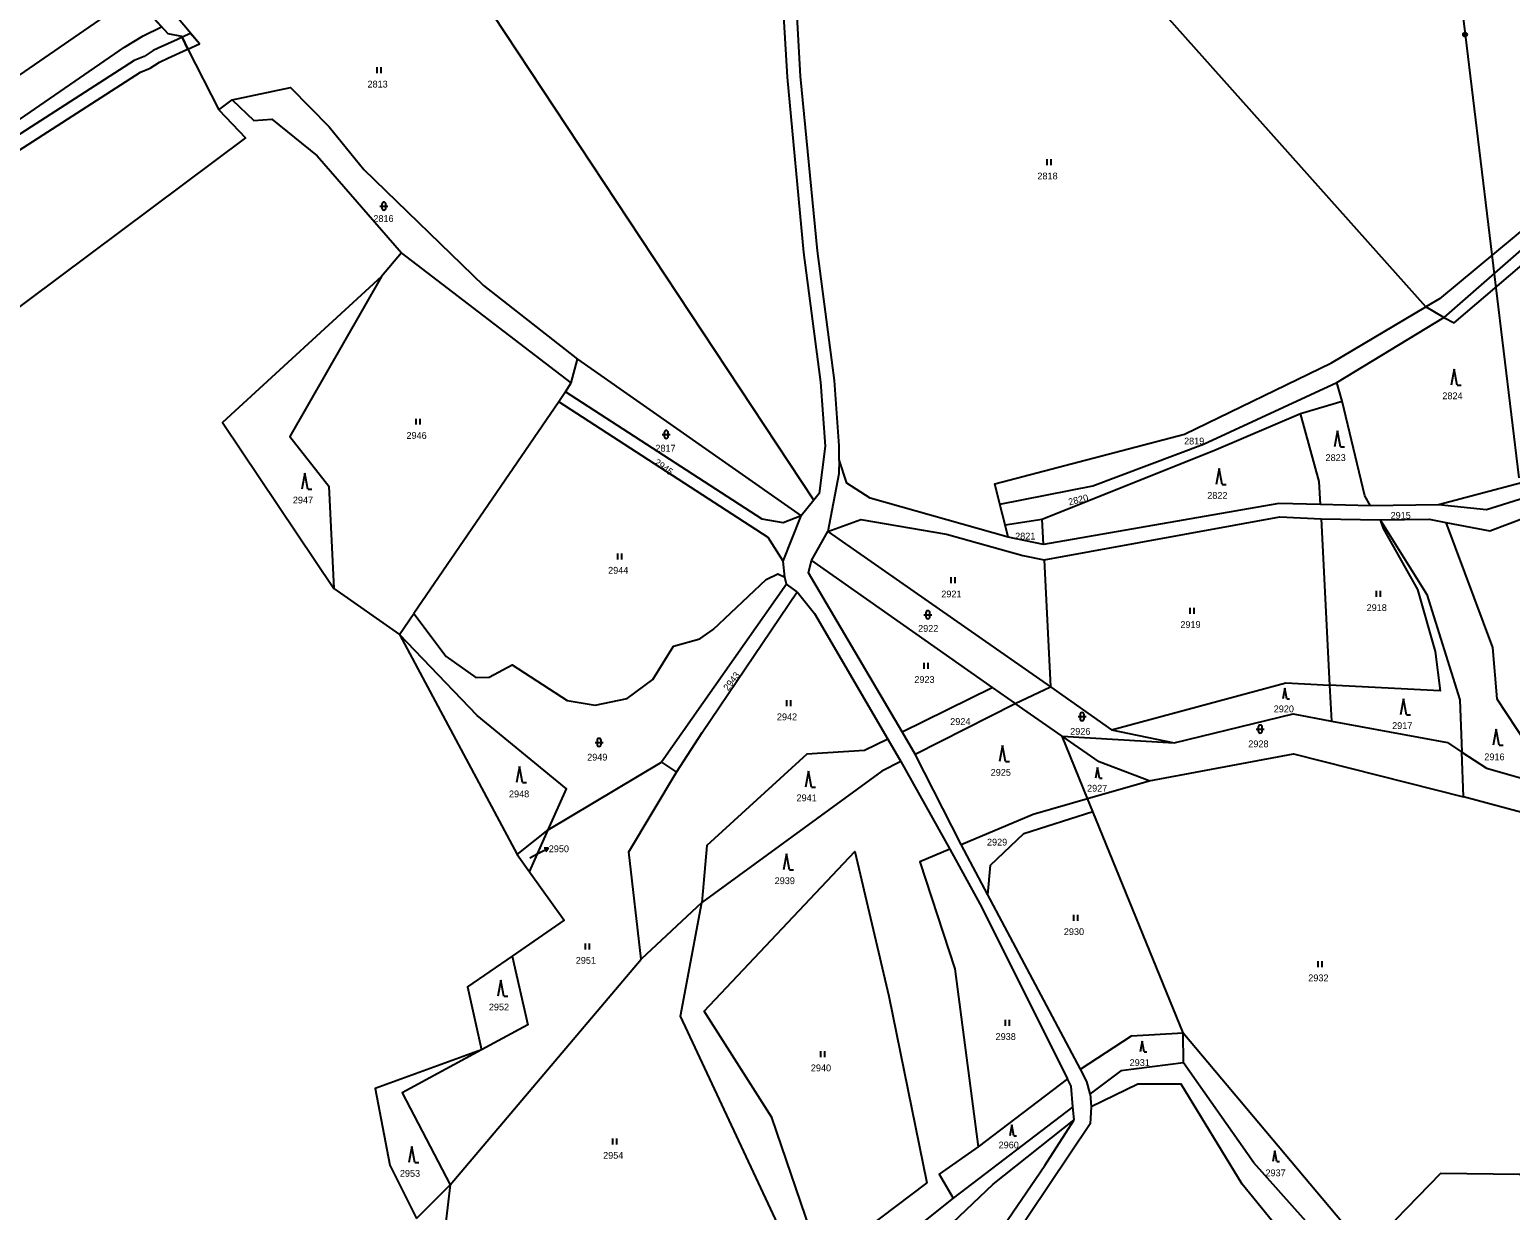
# Model space of a CAD drawing. Extents: x -504988 to -494607, y -1123820 to -1114018.
# Drawn here: x -497021.1 to -496650.7, y -1121578.3 to -1121283 of the extents above; entities that cross this region are included whole.
import ezdxf

# ---------------------------------------------------------------- set-up
doc = ezdxf.new("R2010")
doc.units = 0
for name, color, linetype in [('Hranice parcel', 7, 'Continuous'), ('Parcelní čísla', 7, 'Continuous'), ('Pop  PČ popisy', 7, 'Continuous'), ('Poz předměty', 7, 'Continuous'), ('Věcná břemena k části', 7, 'Continuous'), ('Značky kultur', 7, 'Continuous')]:
    doc.layers.add(name, color=color, linetype=linetype)

msp = doc.modelspace()

# ---------------------------------------------------------------- linework, layer by layer
at = {"layer": 'Hranice parcel'}
for p, q in [((-496824.94, -1121400.71), (-496928.4, -1121244.15)), ((-496981.48, -1121287.89), (-496973.8, -1121303.07)), ((-496973.8, -1121303.07), (-496970.4, -1121300.6)), ((-496928.1, -1121338.83), (-496933.09, -1121344.78)), ((-496885.6, -1121371.41), (-496928.1, -1121338.83)), ((-496667.38, -1121355.04), (-496671.83, -1121352.39)), ((-496694.09, -1121371.3), (-496667.38, -1121355.04)), ((-496885.6, -1121371.41), (-496884.09, -1121365.43)), ((-496884.09, -1121365.43), (-496828.07, -1121404.66)), ((-496887.05, -1121373.63), (-496885.6, -1121371.41)), ((-496692.78, -1121375.94), (-496694.09, -1121371.3)), ((-496887.05, -1121373.63), (-496888.69, -1121376.14)), ((-496888.69, -1121376.14), (-496924.95, -1121429.06)), ((-496703.19, -1121379.08), (-496692.78, -1121375.94)), ((-496824.94, -1121400.71), (-496828.07, -1121404.66)), ((-496832.57, -1121416.01), (-496828.07, -1121404.66)), ((-496777.11, -1121406.92), (-496778.37, -1121401.76)), ((-496685.69, -1121402.16), (-496698.17, -1121401.84)), ((-496668.66, -1121401.9), (-496685.69, -1121402.16)), ((-496825.49, -1121415.83), (-496821.43, -1121408.53)), ((-496821.43, -1121408.53), (-496765.73, -1121447.42)), ((-496777.11, -1121406.92), (-496767.82, -1121405.47)), ((-496776.29, -1121410), (-496777.11, -1121406.92)), ((-496767.51, -1121411.82), (-496767.82, -1121405.47)), ((-496698, -1121405.35), (-496683.24, -1121405.64)), ((-496698, -1121405.35), (-496695.91, -1121446.98)), ((-496767.51, -1121411.82), (-496776.29, -1121410)), ((-496832.23, -1121419.94), (-496832.57, -1121416.01)), ((-496825.49, -1121415.83), (-496780.3, -1121447.56)), ((-496767.3, -1121415.62), (-496765.73, -1121447.42)), ((-496831.81, -1121421.77), (-496832.23, -1121419.94)), ((-496945.04, -1121422.83), (-496928.54, -1121434.3)), ((-496831.81, -1121421.77), (-496863.07, -1121466.22)), ((-496829.09, -1121423.64), (-496831.81, -1121421.77)), ((-496928.54, -1121434.3), (-496924.95, -1121429.06)), ((-496928.54, -1121434.3), (-496899.13, -1121489.34)), ((-496802.88, -1121458.7), (-496780.3, -1121447.56)), ((-496780.3, -1121447.56), (-496774.61, -1121451.55)), ((-496774.61, -1121451.55), (-496765.73, -1121447.42)), ((-496765.73, -1121447.42), (-496750.47, -1121458.17)), ((-496695.91, -1121446.98), (-496695.46, -1121455.98)), ((-496799.61, -1121464.28), (-496774.61, -1121451.55)), ((-496762.86, -1121459.74), (-496774.61, -1121451.55)), ((-496806.44, -1121460.46), (-496803.16, -1121466.09)), ((-496799.61, -1121464.28), (-496802.88, -1121458.7)), ((-496762.86, -1121459.74), (-496734.81, -1121461.39)), ((-496756.48, -1121475.34), (-496762.86, -1121459.74)), ((-496750.47, -1121458.17), (-496734.81, -1121461.39)), ((-496788.09, -1121486.83), (-496799.61, -1121464.28)), ((-496662.4, -1121474.88), (-496662.87, -1121463.73)), ((-496891.35, -1121483.17), (-496863.07, -1121466.22)), ((-496863.07, -1121466.22), (-496859.31, -1121468.79)), ((-496803.16, -1121466.09), (-496790.92, -1121488.01)), ((-496756.48, -1121475.34), (-496741.08, -1121470.91)), ((-496755.17, -1121478.55), (-496756.48, -1121475.34)), ((-496620.4, -1121486.22), (-496662.4, -1121474.88)), ((-496732.53, -1121533.92), (-496755.17, -1121478.55)), ((-496899.13, -1121489.34), (-496891.35, -1121483.17)), ((-496896.02, -1121493.69), (-496891.35, -1121483.17)), ((-496899.13, -1121489.34), (-496896.02, -1121493.69)), ((-496781.41, -1121499.41), (-496788.09, -1121486.83)), ((-496852.92, -1121501.35), (-496868.16, -1121515.55)), ((-496758.24, -1121543.03), (-496781.41, -1121499.41)), ((-496915.94, -1121571.97), (-496868.16, -1121515.55)), ((-496732.5, -1121541.44), (-496732.53, -1121533.92)), ((-496732.53, -1121533.92), (-496679.69, -1121596.75)), ((-496761.51, -1121545.43), (-496783.8, -1121562.43)), ((-496755.85, -1121549.23), (-496755.6, -1121552.41)), ((-496760.11, -1121552.45), (-496790.08, -1121575.29)), ((-496759.8, -1121555.72), (-496760.11, -1121552.45)), ((-496924.29, -1121580.35), (-496915.94, -1121571.97)), ((-496915.94, -1121571.97), (-496920.35, -1121610.08)), ((-496790.08, -1121575.29), (-496817.45, -1121597.02))]:
    msp.add_line(p, q, dxfattribs=at)
for points in [[(-496848.25, -1121142.03), (-496843.63, -1121149.55), (-496842.8, -1121152.45), (-496838.16, -1121184.95), (-496831.64, -1121294.95), (-496827.52, -1121338.76), (-496823.26, -1121371.18), (-496822.08, -1121387.23), (-496823.6, -1121399.02), (-496824.94, -1121400.71)], [(-496671.83, -1121352.39), (-496785.15, -1121225.31), (-496830.93, -1121246.77)], [(-497027.04, -1121239.69), (-496986.49, -1121284.04), (-496983.12, -1121284.65), (-496981.48, -1121287.89)], [(-496981.48, -1121287.89), (-496978.57, -1121286.57), (-497015.21, -1121242.93)], [(-496818.64, -1121390.63), (-496818.58, -1121387.13), (-496819.78, -1121370.83), (-496824.04, -1121338.37), (-496828.25, -1121294.69), (-496830.93, -1121246.77)], [(-496970.4, -1121300.6), (-496955.8, -1121297.55), (-496946.16, -1121307.32), (-496937.53, -1121318.02), (-496907.55, -1121347.01), (-496884.09, -1121365.43)], [(-496970.4, -1121300.6), (-496965, -1121305.73), (-496960.54, -1121305.42), (-496949.18, -1121314.58), (-496928.1, -1121338.83)], [(-496973.8, -1121303.07), (-496967.1, -1121310.13), (-497060.54, -1121379.84), (-497153.97, -1121449.54), (-497260.82, -1121531.25), (-497367.67, -1121612.95), (-497514.07, -1121725.27), (-497650.99, -1121827.6), (-497729.46, -1121888.34), (-497836.33, -1121970.93), (-497882.09, -1122005.22)], [(-496622.71, -1121308.03), (-496636.01, -1121323.43), (-496668.45, -1121350.39), (-496671.83, -1121352.39)], [(-496622.71, -1121308.03), (-496628.61, -1121321.12), (-496667.38, -1121355.04)], [(-496667.38, -1121355.04), (-496664.77, -1121356.36), (-496626.79, -1121324.03), (-496643.72, -1121366.96), (-496641.34, -1121368.36), (-496625.44, -1121332.21)], [(-496933.09, -1121344.78), (-496972.87, -1121381.29), (-496945.04, -1121422.83)], [(-496933.09, -1121344.78), (-496956.02, -1121384.82), (-496946.29, -1121397.26), (-496945.04, -1121422.83)], [(-496778.37, -1121401.76), (-496779.64, -1121396.6), (-496732.23, -1121384.19), (-496695.49, -1121366.35), (-496671.83, -1121352.39)], [(-496620.34, -1121360.24), (-496634.95, -1121356.72), (-496633.53, -1121372.93), (-496638.31, -1121372.79), (-496639.77, -1121389.71), (-496646.34, -1121396), (-496668.66, -1121401.9)], [(-496778.37, -1121401.76), (-496755.18, -1121397.16), (-496727.48, -1121386.73), (-496694.09, -1121371.3)], [(-496828.07, -1121404.66), (-496832.6, -1121406.4), (-496837.86, -1121405.5), (-496887.05, -1121373.63)], [(-496832.57, -1121416.01), (-496836.36, -1121410.03), (-496888.69, -1121376.14)], [(-496767.82, -1121405.47), (-496724.29, -1121388.08), (-496703.19, -1121379.08)], [(-496698.17, -1121401.84), (-496698.51, -1121396.09), (-496703.19, -1121379.08)], [(-496685.69, -1121402.16), (-496687.11, -1121399.61), (-496692.78, -1121375.94)], [(-496818.64, -1121390.63), (-496818.69, -1121394.14), (-496821.43, -1121408.53)], [(-496776.29, -1121410), (-496810.86, -1121400.24), (-496816.65, -1121396.46), (-496818.64, -1121390.63)], [(-496558.08, -1121460.12), (-496564.28, -1121460.43), (-496569.68, -1121458.96), (-496588.54, -1121447.1), (-496598.53, -1121439.12), (-496623.23, -1121401.96), (-496630.14, -1121397.89), (-496637.5, -1121397.15), (-496656.69, -1121403.1), (-496668.66, -1121401.9)], [(-496698.17, -1121401.84), (-496708.6, -1121401.57), (-496767.51, -1121411.82)], [(-496767.3, -1121415.62), (-496708.4, -1121404.87), (-496698, -1121405.35)], [(-496666.89, -1121406.29), (-496655.87, -1121408.36), (-496642.6, -1121403.41), (-496634.03, -1121402.52), (-496627.92, -1121405.3), (-496623.56, -1121408.29), (-496600.71, -1121442.49), (-496590.86, -1121450.37)], [(-496821.43, -1121408.53), (-496813.17, -1121405.57), (-496791.74, -1121409.22), (-496772.62, -1121414.57), (-496767.3, -1121415.62)], [(-496683.24, -1121405.64), (-496682.54, -1121407.78), (-496673.95, -1121423.07), (-496669.56, -1121438.61), (-496668.23, -1121448.39), (-496695.91, -1121446.98)], [(-496683.24, -1121405.64), (-496671.01, -1121405.51), (-496666.89, -1121406.29)], [(-496683.24, -1121405.64), (-496671.63, -1121424.3), (-496663.33, -1121450.7), (-496662.87, -1121463.73)], [(-496666.89, -1121406.29), (-496655.19, -1121437.57), (-496654.1, -1121450.38), (-496646.83, -1121461.45), (-496616.96, -1121474.47)], [(-496802.88, -1121458.7), (-496826.24, -1121418.88), (-496825.49, -1121415.83)], [(-496924.95, -1121429.06), (-496916.88, -1121439.84), (-496909.45, -1121445.04), (-496906.15, -1121445), (-496900.38, -1121441.89), (-496886.67, -1121450.86), (-496879.64, -1121452.02), (-496871.65, -1121450.35), (-496865.24, -1121445.55), (-496860.04, -1121437.24), (-496853.43, -1121435.4), (-496850.09, -1121433.09), (-496836.83, -1121420.56), (-496833.93, -1121419.13), (-496832.23, -1121419.94)], [(-496859.31, -1121468.79), (-496852.85, -1121458.85), (-496829.09, -1121423.64)], [(-496829.09, -1121423.64), (-496824.76, -1121429.05), (-496806.44, -1121460.46)], [(-496891.35, -1121483.17), (-496886.78, -1121472.9), (-496909.18, -1121454.59), (-496928.54, -1121434.3)], [(-496750.47, -1121458.17), (-496706.91, -1121446.42), (-496695.91, -1121446.98)], [(-496734.81, -1121461.39), (-496705.03, -1121454.2), (-496695.46, -1121455.98)], [(-496695.46, -1121455.98), (-496666.47, -1121461.37), (-496662.87, -1121463.73)], [(-496806.44, -1121460.46), (-496812.23, -1121463.32), (-496826.72, -1121464.23), (-496851.72, -1121487.12), (-496852.92, -1121501.35)], [(-496741.08, -1121470.91), (-496753.54, -1121466.19), (-496762.86, -1121459.74)], [(-496741.08, -1121470.91), (-496704.99, -1121464.18), (-496662.4, -1121474.88)], [(-496662.87, -1121463.73), (-496656.68, -1121467.79), (-496606.05, -1121482.18)], [(-496803.16, -1121466.09), (-496807.96, -1121468.54), (-496852.92, -1121501.35)], [(-496868.16, -1121515.55), (-496871.17, -1121488.67), (-496859.31, -1121468.79)], [(-496788.09, -1121486.83), (-496770.11, -1121479.26), (-496756.48, -1121475.34)], [(-496781.41, -1121499.41), (-496780.71, -1121491.98), (-496772.38, -1121484.05), (-496755.17, -1121478.55)], [(-496796.66, -1121571.42), (-496819.87, -1121588.98), (-496825.78, -1121583.49), (-496835.43, -1121555.08), (-496852.36, -1121528.53), (-496814.67, -1121488.62), (-496806.18, -1121524.73), (-496796.66, -1121571.42)], [(-496790.92, -1121488.01), (-496798.45, -1121491.19), (-496789.69, -1121517.91), (-496783.8, -1121562.43)], [(-496790.92, -1121488.01), (-496783.41, -1121501.67), (-496761.51, -1121545.43)], [(-496896.02, -1121493.69), (-496887.42, -1121505.73), (-496900.39, -1121514.74)], [(-496832.12, -1121585.69), (-496858.26, -1121529.75), (-496852.92, -1121501.35)], [(-496900.39, -1121514.74), (-496911.53, -1121522.47), (-496908.04, -1121538.23)], [(-496900.39, -1121514.74), (-496896.44, -1121531.96), (-496908.04, -1121538.23)], [(-496758.24, -1121543.03), (-496745.45, -1121534.72), (-496732.53, -1121533.92)], [(-496908.04, -1121538.23), (-496934.65, -1121547.87), (-496930.98, -1121567.06), (-496924.29, -1121580.35)], [(-496908.04, -1121538.23), (-496927.88, -1121548.95), (-496915.94, -1121571.97)], [(-496732.5, -1121541.44), (-496748.16, -1121543.43), (-496755.85, -1121549.23)], [(-496686.13, -1121598.72), (-496714.85, -1121566.43), (-496732.5, -1121541.44)], [(-496760.11, -1121552.45), (-496760.6, -1121547.25), (-496761.51, -1121545.43)], [(-496755.85, -1121549.23), (-496756.69, -1121546.13), (-496758.24, -1121543.03)], [(-496758.17, -1121707.39), (-496746.55, -1121684.08), (-496750.96, -1121648.86), (-496743.63, -1121632.12), (-496731.41, -1121616.02), (-496714.73, -1121605.77), (-496695.15, -1121599.6), (-496717.82, -1121571.78), (-496733.06, -1121546.75), (-496743.91, -1121546.74), (-496755.6, -1121552.41)], [(-496755.6, -1121552.41), (-496755.84, -1121556.71), (-496786.34, -1121602.24), (-496790.93, -1121617.84), (-496789.5, -1121631.19), (-496787.93, -1121654.85), (-496788.06, -1121674.86), (-496781.27, -1121683.85), (-496768.89, -1121690.38), (-496761.24, -1121698.29), (-496758.17, -1121707.39)], [(-496810.31, -1121600.51), (-496780.06, -1121571.77), (-496759.8, -1121555.72)], [(-496794.98, -1121617.43), (-496790.01, -1121600.53), (-496767.13, -1121567.08), (-496759.8, -1121555.72)], [(-496783.8, -1121562.43), (-496793.6, -1121569.28), (-496790.08, -1121575.29)], [(-496628.32, -1121586.51), (-496631.2, -1121576.69), (-496648.43, -1121569.4), (-496668.19, -1121569.15), (-496679.47, -1121580.69), (-496681.86, -1121588.4), (-496679.69, -1121596.75)]]:
    msp.add_lwpolyline(points, dxfattribs=at)
at = {"layer": 'Pop  PČ popisy'}
for p, q in [((-496895.98, -1121490.14), (-496893.95, -1121489.13)), ((-496893.95, -1121489.13), (-496891.28, -1121487.77)), ((-496891.28, -1121487.77), (-496892.4, -1121487.78)), ((-496891.28, -1121487.77), (-496891.94, -1121488.67))]:
    msp.add_line(p, q, dxfattribs=at)
at = {"layer": 'Poz předměty'}
for p, q in [((-496673.23, -1121192.05), (-496662.04, -1121284.27)), ((-496662.04, -1121284.27), (-496648.56, -1121395.11))]:
    msp.add_line(p, q, dxfattribs=at)
for radius in [0.5, 0.4, 0.3, 0.2, 0.1]:
    msp.add_circle((-496662.04, -1121284.27), radius, dxfattribs=at)
at = {"layer": 'Věcná břemena k části'}
for points in [[(-497811.58, -1121879.55), (-497093.4, -1121353.6), (-497092.05, -1121352.64), (-496997.34, -1121287.45), (-496992.71, -1121284.59), (-496988.08, -1121282.31), (-496994.53, -1121275.24), (-496997.17, -1121276.54), (-497002.55, -1121279.88), (-497097.27, -1121345.06), (-497098.84, -1121346.17), (-497800.72, -1121860.2), (-497964.42, -1121980.09), (-497969.75, -1121983.99), (-497964.15, -1121991.28), (-497958.8, -1121987.36)], [(-496980.82, -1121283.97), (-496982.96, -1121284.96), (-496981.48, -1121287.89), (-496978.57, -1121286.57)]]:
    msp.add_lwpolyline(points, close=True, dxfattribs=at)
msp.add_lwpolyline([(-497026.35, -1121314.94), (-496993.36, -1121293.7), (-496990.92, -1121292.65), (-496988.6, -1121291.18), (-496986.5, -1121290.22), (-496981.78, -1121288.05), (-496981.48, -1121287.89), (-496982.96, -1121284.96), (-496984.1, -1121285.48), (-496988.96, -1121287.72), (-496990.18, -1121288.28), (-496992.46, -1121289.73), (-496994.92, -1121290.78), (-497028.19, -1121312.2)], dxfattribs=at)
at = {"layer": 'Značky kultur'}
for p, q in [((-496934.12, -1121293.97), (-496934.12, -1121292.47)), ((-496933.12, -1121293.97), (-496933.12, -1121292.47)), ((-496766.55, -1121316.95), (-496766.55, -1121315.45)), ((-496765.55, -1121316.95), (-496765.55, -1121315.45)), ((-496933.48, -1121327.19), (-496931.48, -1121327.19)), ((-496932.98, -1121326.69), (-496932.98, -1121327.69)), ((-496931.98, -1121327.69), (-496931.98, -1121326.69)), ((-496664.75, -1121367.93), (-496665.5, -1121371.93)), ((-496664, -1121371.93), (-496664.75, -1121367.93)), ((-496664, -1121371.93), (-496663, -1121371.93)), ((-496924.37, -1121381.84), (-496924.37, -1121380.34)), ((-496923.37, -1121381.84), (-496923.37, -1121380.34)), ((-496862.86, -1121384.29), (-496860.86, -1121384.29)), ((-496862.36, -1121383.79), (-496862.36, -1121384.79)), ((-496861.36, -1121384.79), (-496861.36, -1121383.79)), ((-496693.97, -1121383.38), (-496694.72, -1121387.38)), ((-496693.22, -1121387.38), (-496693.97, -1121383.38)), ((-496693.22, -1121387.38), (-496692.22, -1121387.38)), ((-496952.28, -1121393.99), (-496953.03, -1121397.99)), ((-496951.53, -1121397.99), (-496952.28, -1121393.99)), ((-496723.56, -1121392.83), (-496724.31, -1121396.83)), ((-496722.81, -1121396.83), (-496723.56, -1121392.83)), ((-496722.81, -1121396.83), (-496721.81, -1121396.83)), ((-496951.53, -1121397.99), (-496950.53, -1121397.99)), ((-496873.93, -1121415.56), (-496873.93, -1121414.06)), ((-496872.93, -1121415.56), (-496872.93, -1121414.06)), ((-496790.59, -1121421.49), (-496790.59, -1121419.99)), ((-496789.59, -1121421.49), (-496789.59, -1121419.99)), ((-496684.21, -1121424.91), (-496684.21, -1121423.41)), ((-496683.21, -1121424.91), (-496683.21, -1121423.41)), ((-496797.4, -1121429.37), (-496795.4, -1121429.37)), ((-496796.9, -1121428.87), (-496796.9, -1121429.87)), ((-496795.9, -1121429.87), (-496795.9, -1121428.87)), ((-496730.79, -1121429.13), (-496730.79, -1121427.63)), ((-496729.79, -1121429.13), (-496729.79, -1121427.63)), ((-496797.33, -1121442.88), (-496797.33, -1121441.38)), ((-496796.33, -1121442.88), (-496796.33, -1121441.38)), ((-496707.12, -1121447.7), (-496707.62, -1121450.38)), ((-496706.62, -1121450.38), (-496707.12, -1121447.7)), ((-496831.71, -1121452.22), (-496831.71, -1121450.72)), ((-496830.71, -1121452.22), (-496830.71, -1121450.72)), ((-496706.62, -1121450.38), (-496705.95, -1121450.38)), ((-496677.48, -1121450.39), (-496678.23, -1121454.39)), ((-496676.73, -1121454.39), (-496677.48, -1121450.39)), ((-496758.84, -1121454.85), (-496756.84, -1121454.85)), ((-496758.34, -1121454.35), (-496758.34, -1121455.35)), ((-496757.34, -1121455.35), (-496757.34, -1121454.35)), ((-496676.73, -1121454.39), (-496675.73, -1121454.39)), ((-496879.16, -1121460.8), (-496879.16, -1121461.8)), ((-496878.16, -1121461.8), (-496878.16, -1121460.8)), ((-496714.29, -1121457.97), (-496712.29, -1121457.97)), ((-496713.79, -1121457.47), (-496713.79, -1121458.47)), ((-496712.79, -1121458.47), (-496712.79, -1121457.47)), ((-496654.27, -1121458), (-496655.02, -1121462)), ((-496653.52, -1121462), (-496654.27, -1121458)), ((-496879.66, -1121461.3), (-496877.66, -1121461.3)), ((-496777.73, -1121462.1), (-496778.48, -1121466.1)), ((-496776.98, -1121466.1), (-496777.73, -1121462.1)), ((-496653.52, -1121462), (-496652.52, -1121462)), ((-496898.55, -1121467.3), (-496899.3, -1121471.3)), ((-496897.8, -1121471.3), (-496898.55, -1121467.3)), ((-496776.98, -1121466.1), (-496775.98, -1121466.1)), ((-496753.96, -1121467.58), (-496754.46, -1121470.26)), ((-496753.46, -1121470.26), (-496753.96, -1121467.58)), ((-496897.8, -1121471.3), (-496896.8, -1121471.3)), ((-496826.29, -1121468.47), (-496827.04, -1121472.47)), ((-496825.54, -1121472.47), (-496826.29, -1121468.47)), ((-496753.46, -1121470.26), (-496752.79, -1121470.26)), ((-496825.54, -1121472.47), (-496824.54, -1121472.47)), ((-496831.76, -1121489.2), (-496832.51, -1121493.2)), ((-496831.01, -1121493.2), (-496831.76, -1121489.2)), ((-496831.01, -1121493.2), (-496830.01, -1121493.2)), ((-496759.94, -1121505.94), (-496759.94, -1121504.44)), ((-496758.94, -1121505.94), (-496758.94, -1121504.44)), ((-496882.03, -1121513.12), (-496882.03, -1121511.62)), ((-496881.03, -1121513.12), (-496881.03, -1121511.62)), ((-496698.8, -1121517.5), (-496698.8, -1121516)), ((-496697.8, -1121517.5), (-496697.8, -1121516)), ((-496903.25, -1121520.79), (-496904, -1121524.79)), ((-496902.5, -1121524.79), (-496903.25, -1121520.79)), ((-496902.5, -1121524.79), (-496901.5, -1121524.79)), ((-496777.01, -1121532.17), (-496777.01, -1121530.67)), ((-496776.01, -1121532.17), (-496776.01, -1121530.67)), ((-496823.22, -1121540.01), (-496823.22, -1121538.51)), ((-496822.22, -1121540.01), (-496822.22, -1121538.51)), ((-496742.79, -1121536.04), (-496743.29, -1121538.72)), ((-496742.29, -1121538.72), (-496742.79, -1121536.04)), ((-496742.29, -1121538.72), (-496741.62, -1121538.72)), ((-496775.38, -1121556.99), (-496775.88, -1121559.67)), ((-496774.88, -1121559.67), (-496775.38, -1121556.99)), ((-496875.18, -1121561.88), (-496875.18, -1121560.38)), ((-496874.18, -1121561.88), (-496874.18, -1121560.38)), ((-496774.88, -1121559.67), (-496774.21, -1121559.67)), ((-496925.51, -1121562.39), (-496926.26, -1121566.39)), ((-496924.76, -1121566.39), (-496925.51, -1121562.39)), ((-496709.59, -1121563.43), (-496710.09, -1121566.11)), ((-496709.09, -1121566.11), (-496709.59, -1121563.43)), ((-496924.76, -1121566.39), (-496923.76, -1121566.39)), ((-496709.09, -1121566.11), (-496708.42, -1121566.11))]:
    msp.add_line(p, q, dxfattribs=at)
for centre, start, end in [((-496932.48, -1121326.69), 0, 180), ((-496932.48, -1121327.69), 180, 359.9879), ((-496861.86, -1121383.79), 0, 180), ((-496861.86, -1121384.79), 180, 359.9879), ((-496796.4, -1121428.87), 0, 180), ((-496796.4, -1121429.87), 180, 359.9879), ((-496757.84, -1121454.35), 0, 180), ((-496757.84, -1121455.35), 180, 359.9879), ((-496713.29, -1121457.47), 0, 180), ((-496878.66, -1121460.8), 0, 180), ((-496713.29, -1121458.47), 180, 359.9879), ((-496878.66, -1121461.8), 180, 359.9879)]:
    msp.add_arc(centre, 0.5, start, end, dxfattribs=at)

# ---------------------------------------------------------------- texts
at = {"layer": 'Parcelní čísla'}
for s, p in [('2813', (-496936.58, -1121297.52)), ('2818', (-496769.01, -1121320.5)), ('2816', (-496935.12, -1121331.14)), ('2824', (-496667.72, -1121375.48)), ('2946', (-496926.83, -1121385.39)), ('2819', (-496732.33, -1121386.79)), ('2817', (-496864.57, -1121388.57)), ('2823', (-496696.94, -1121390.93)), ('2947', (-496955.25, -1121401.54)), ('2822', (-496726.53, -1121400.38)), ('2915', (-496680.67, -1121405.38)), ('2821', (-496774.58, -1121410.56)), ('2944', (-496876.39, -1121419.11)), ('2921', (-496793.05, -1121425.04)), ('2918', (-496686.67, -1121428.46)), ('2919', (-496733.25, -1121432.68)), ('2922', (-496798.85, -1121433.65)), ('2923', (-496799.79, -1121446.43)), ('2920', (-496709.9, -1121453.77)), ('2942', (-496834.17, -1121455.77)), ('2924', (-496790.82, -1121456.94)), ('2917', (-496680.28, -1121457.96)), ('2926', (-496760.81, -1121459.4)), ('2928', (-496716.26, -1121462.52)), ('2949', (-496881.63, -1121465.85)), ('2916', (-496657.22, -1121465.77)), ('2925', (-496780.7, -1121469.65)), ('2927', (-496756.59, -1121473.62)), ('2948', (-496901.19, -1121475.04)), ('2941', (-496829.26, -1121476.02)), ('2929', (-496781.63, -1121487.1)), ('2950', (-496891.24, -1121488.77)), ('2939', (-496834.73, -1121496.75)), ('2930', (-496762.4, -1121509.49)), ('2951', (-496884.49, -1121516.67)), ('2932', (-496701.26, -1121521.05)), ('2952', (-496906.22, -1121528.34)), ('2938', (-496779.47, -1121535.72)), ('2940', (-496825.68, -1121543.56)), ('2931', (-496745.94, -1121542.23)), ('2954', (-496877.64, -1121565.43)), ('2960', (-496778.72, -1121562.84)), ('2953', (-496928.48, -1121569.94)), ('2937', (-496711.97, -1121569.81))]:
    msp.add_text(s, height=1.7, dxfattribs=at).set_placement(p)
for s, rotation, p in [('2945', 324, (-496865.01, -1121391.63)), ('2820', 14, (-496761.04, -1121402.06)), ('2943', 53, (-496846.36, -1121448.53))]:
    msp.add_text(s, height=1.7, rotation=rotation, dxfattribs=at).set_placement(p)

doc.saveas('drawing.dxf')
